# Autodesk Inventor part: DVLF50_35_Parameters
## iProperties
Created: 2010-03
Part Number: DVLF50_35_Parameters
Document SubType Name: Modeling
Designer: TB
Density: 1 g/cm^3
Slaglengde: 100.000 mm
Vinkel_Plussport: 0.00 deg
Vinkel_Minusport: 0.00 deg
Forlengelse_rør: 0.000 mm
Author: TB
